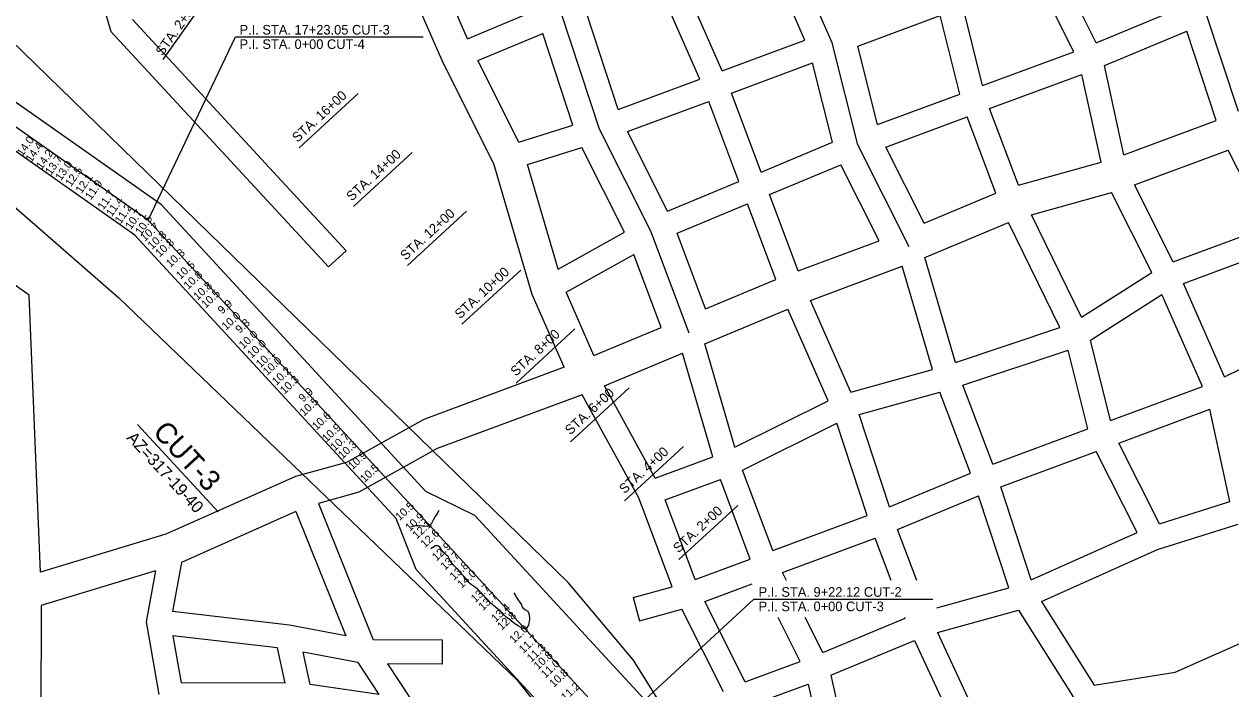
# Model space of a CAD drawing. Extents: x 503330 to 511530, y 1310349 to 1316149.
# Drawn here: x 506410 to 509426, y 1313078 to 1314740 of the extents above; entities that cross this region are included whole.
import ezdxf

# ---------------------------------------------------------------- set-up
doc = ezdxf.new("R2010")
doc.units = 0
for name, color, linetype in [('Level 1', 7, 'Continuous'), ('Level 13', 7, 'Continuous'), ('Level 14', 7, 'Continuous'), ('Level 23', 7, 'Continuous'), ('Level 32', 7, 'Continuous'), ('Level 49', 7, 'Continuous'), ('Level 5', 7, 'Continuous'), ('Level 50', 7, 'Continuous'), ('Level 51', 7, 'Continuous'), ('Level 56', 7, 'Continuous'), ('Level 6', 7, 'Continuous')]:
    doc.layers.add(name, color=color, linetype=linetype)

msp = doc.modelspace()

# ---------------------------------------------------------------- linework, layer by layer
at = {"layer": 'Level 1'}
for points in [[(507377.3, 1313484.3), (507382.6, 1313485.7), (507386.6, 1313486.1), (507392.1, 1313486.3), (507398.9, 1313486.3), (507405.5, 1313486.1), (507411.9, 1313485.7), (507418.2, 1313485.2), (507424, 1313487.5), (507429.2, 1313492.7), (507433.9, 1313500.8), (507438, 1313508), (507441.6, 1313514.3), (507447.6, 1313525.3)], [(507580.8, 1313288.9), (507577.7, 1313291.9), (507574.6, 1313295), (507571.5, 1313298.2), (507567.9, 1313302.1), (507563.8, 1313306.6), (507559.2, 1313311.7), (507554.3, 1313316.9), (507549, 1313322), (507543.5, 1313327.2), (507538.3, 1313331.6), (507533.4, 1313335.3), (507528.7, 1313338.4), (507524.3, 1313342), (507520.1, 1313346.1), (507516.2, 1313350.9), (507512.9, 1313354.9), (507510.2, 1313358.2), (507508.1, 1313360.7), (507505.7, 1313363.6), (507503.1, 1313366.7), (507500.2, 1313370.1), (507496, 1313374.7), (507490.6, 1313380.4), (507483.9, 1313387.3), (507478.7, 1313393.6), (507475, 1313399.3), (507472.8, 1313404.5), (507469.9, 1313409), (507466.4, 1313412.8), (507462.3, 1313415.9), (507458, 1313420.3), (507453.7, 1313425.9), (507449.2, 1313432.8), (507444.3, 1313436.1), (507438.9, 1313435.9), (507427.1, 1313428.4)], [(507634.1, 1313318.6), (507638.1, 1313311.4), (507639.7, 1313308.8), (507640.7, 1313307.2), (507641.2, 1313306.5), (507643, 1313303.9), (507646, 1313299.4), (507650.3, 1313292.9), (507653.2, 1313288.1), (507654.7, 1313284.8), (507654.8, 1313283.1), (507657.2, 1313280.5), (507661.9, 1313277), (507669, 1313272.6), (507672.8, 1313264.5), (507673.4, 1313252.8), (507670.7, 1313237.4), (507665.2, 1313229.5), (507656.7, 1313228.9), (507645.4, 1313235.7), (507637, 1313241), (507631.6, 1313244.8), (507629.2, 1313247.1), (507626.1, 1313249.6), (507622.5, 1313252.2), (507618.4, 1313255), (507614.6, 1313258.1), (507611.3, 1313261.5), (507608.4, 1313265.2), (507604.5, 1313269.3), (507599.4, 1313273.7), (507593.3, 1313278.5), (507588.2, 1313282.6), (507584, 1313286), (507580.8, 1313288.9)]]:
    msp.add_lwpolyline(points, dxfattribs=at)
at = {"layer": 'Level 13'}
for p, q in [((508430.3, 1314693.3), (508302.2, 1314984.7)), ((507848.3, 1314477.4), (507752.6, 1314768.6)), ((508493.9, 1314438.6), (508430.3, 1314693.3)), ((507976.5, 1314222.4), (507848.3, 1314477.4)), ((508622.1, 1314183.7), (508493.9, 1314438.6)), ((508072.4, 1313967.6), (507976.5, 1314222.4))]:
    msp.add_line(p, q, dxfattribs=at)
at = {"layer": 'Level 14'}
for p, q in [((508361.9, 1314699.9), (508258, 1314936.2)), ((507895.3, 1314526.8), (507817.5, 1314763.2)), ((507781.8, 1314487.7), (507706.5, 1314716.8)), ((508543.2, 1314488.9), (508494.2, 1314685.1)), ((508430.6, 1314444.7), (508381, 1314643.1)), ((508018.5, 1314272.5), (507918.5, 1314471.4)), ((507910.6, 1314220), (507804.1, 1314431.9)), ((508659.6, 1314242.7), (508564.1, 1314432.7)), ((508547.4, 1314198.6), (508451.9, 1314388.6)), ((508113.7, 1314028.2), (508042.5, 1314217.5)), ((508002.9, 1313981.9), (507934.2, 1314164.5))]:
    msp.add_line(p, q, dxfattribs=at)
at = {"layer": 'Level 23'}
for p, q in [((507518.7, 1314703.4), (507447.5, 1314865.4)), ((507457.7, 1314643.5), (507369, 1314845.3)), ((507584.7, 1314390.8), (507457.7, 1314643.5)), ((507647, 1314444.9), (507544.4, 1314649.1)), ((509159.1, 1314413.5), (509389.7, 1314499.1)), ((509185.7, 1314338), (509420.1, 1314425)), ((507680, 1314064.3), (507584.7, 1314390.8)), ((507744.9, 1314127.5), (507668.6, 1314388.8)), ((508895.7, 1314337.4), (509101.9, 1314394.6)), ((508928.1, 1314263.4), (509128.2, 1314318.9)), ((508659.6, 1314242.7), (508839, 1314317.6)), ((508661.2, 1314156.7), (508870.7, 1314244.2)), ((508345.2, 1314123.5), (508547.4, 1314198.6)), ((508375.4, 1314049.4), (508605.1, 1314134.7)), ((508113.7, 1314028.2), (508289.3, 1314101.6)), ((507760, 1313882.2), (507680, 1314064.3)), ((507834.5, 1313911.5), (507764.9, 1314070)), ((508111.6, 1313940.6), (508319.5, 1314027.5)), ((507834.5, 1313911.5), (508002.9, 1313981.9)), ((507861, 1313835.9), (508055.9, 1313917.3)), ((507760, 1313882.2), (507409, 1313751.9)), ((507804.8, 1313813.5), (507442.6, 1313679.1)), ((507409, 1313751.9), (507341.6, 1313714.3)), ((507341.6, 1313714.3), (507216.3, 1313644.4)), ((507442.6, 1313679.1), (507380.5, 1313644.5)), ((507216.3, 1313644.4), (507088.8, 1313609.1)), ((507380.5, 1313644.5), (507246.9, 1313569.9)), ((507088.8, 1313609.1), (506764.9, 1313464.7)), ((507246.9, 1313569.9), (507146.4, 1313542)), ((507089.8, 1313521.9), (506803.5, 1313394.2)), ((506764.9, 1313464.7), (506451.4, 1313369.7)), ((506738.6, 1313373.1), (506453.3, 1313286.6))]:
    msp.add_line(p, q, dxfattribs=at)
at = {"layer": 'Level 32'}
for p, q in [((509090.1, 1314693), (508990, 1314892.1)), ((509034, 1314671), (508934.1, 1314869.8)), ((506627.9, 1314721.2), (506592.9, 1314841.3)), ((508099.1, 1314602.4), (507995.7, 1314837.7)), ((508155.4, 1314623.3), (508051.5, 1314859.6)), ((507518.7, 1314703.4), (507683.6, 1314772.3)), ((508805.9, 1314586.4), (508756.3, 1314784.8)), ((509090.1, 1314693), (509299.2, 1314780.4)), ((509445.3, 1314522), (509363.4, 1314771)), ((507215.1, 1314173.7), (506681.6, 1314751.5)), ((508494.2, 1314685.1), (508700.3, 1314761.5)), ((508749.3, 1314565.4), (508700.3, 1314761.5)), ((507171, 1314133), (506627.9, 1314721.2)), ((507544.4, 1314649.1), (507706.5, 1314716.8)), ((509110.5, 1314636.5), (509316.2, 1314722.5)), ((509389.7, 1314499.1), (509316.2, 1314722.5)), ((508155.4, 1314623.3), (508361.9, 1314699.9)), ((508805.9, 1314586.4), (509034, 1314671)), ((508178, 1314567.7), (508381, 1314643.1)), ((509159.1, 1314413.5), (509110.5, 1314636.5)), ((507895.3, 1314526.8), (508099.1, 1314602.4)), ((508823.6, 1314529), (509053.9, 1314614.4)), ((509101.9, 1314394.6), (509053.9, 1314614.4)), ((508252.3, 1314370.2), (508178, 1314567.7)), ((508543.2, 1314488.9), (508749.3, 1314565.4)), ((507918.5, 1314471.4), (508121.8, 1314546.9)), ((508197, 1314347), (508121.8, 1314546.9)), ((508564.1, 1314432.7), (508767.3, 1314508.1)), ((508839, 1314317.6), (508767.3, 1314508.1)), ((508895.7, 1314337.4), (508823.6, 1314529)), ((507647, 1314444.9), (507781.8, 1314487.7)), ((508252.3, 1314370.2), (508430.6, 1314444.7)), ((507668.6, 1314388.8), (507804.1, 1314431.9)), ((509516.7, 1314233), (509420.1, 1314425)), ((508273.5, 1314314), (508451.9, 1314388.6)), ((508018.5, 1314272.5), (508197, 1314347)), ((509228.6, 1314119.3), (509128.2, 1314318.9)), ((509282.3, 1314146), (509185.7, 1314338)), ((508042.5, 1314217.5), (508218.1, 1314290.8)), ((508289.3, 1314101.6), (508218.1, 1314290.8)), ((508345.2, 1314123.5), (508273.5, 1314314)), ((509053.2, 1314007.3), (508928.1, 1314263.4)), ((508999, 1313981.6), (508870.7, 1314244.2)), ((509282.3, 1314146), (509516.7, 1314233)), ((507744.9, 1314127.5), (507910.6, 1314220)), ((507171, 1314133), (507215.1, 1314173.7)), ((509307.8, 1314091.5), (509543.8, 1314179.1)), ((507764.9, 1314070), (507934.2, 1314164.5)), ((508737.8, 1313894.4), (508661.2, 1314156.7)), ((508680.4, 1313876.9), (508605.1, 1314134.7)), ((509053.2, 1314007.3), (509228.6, 1314119.3)), ((509410.4, 1313858.1), (509307.8, 1314091.5)), ((508476.2, 1313820.2), (508375.4, 1314049.4)), ((509075.3, 1313950.3), (509254.2, 1314064.4)), ((509355.3, 1313834.3), (509254.2, 1314064.4)), ((508420.2, 1313798.5), (508319.5, 1314027.5)), ((508737.8, 1313894.4), (508999, 1313981.6)), ((509410.4, 1313858.1), (509646.4, 1313975)), ((508186.8, 1313682.8), (508111.6, 1313940.6)), ((509125.6, 1313749), (509075.3, 1313950.3)), ((508131.4, 1313658.4), (508055.9, 1313917.3)), ((508756.8, 1313837.5), (509019.8, 1313925.2)), ((509069, 1313728), (509019.8, 1313925.2)), ((508476.2, 1313820.2), (508680.4, 1313876.9)), ((507987.9, 1313605.2), (507861, 1313835.9)), ((508831.2, 1313639.8), (508756.8, 1313837.5)), ((507946.8, 1313555.5), (507804.8, 1313813.5)), ((508497.5, 1313763.9), (508699.3, 1313819.9)), ((508775.4, 1313617.8), (508699.3, 1313819.9)), ((509125.6, 1313749), (509355.3, 1313834.3)), ((508186.8, 1313682.8), (508420.2, 1313798.5)), ((509146.5, 1313692.8), (509373.7, 1313777.1)), ((509424, 1313546.5), (509373.7, 1313777.1)), ((508573.3, 1313533.3), (508497.5, 1313763.9)), ((508205.7, 1313625.2), (508441.5, 1313742.1)), ((508517.4, 1313511.2), (508441.5, 1313742.1)), ((508831.2, 1313639.8), (509069, 1313728)), ((509248.1, 1313490.6), (509146.5, 1313692.8)), ((507987.9, 1313605.2), (508131.4, 1313658.4)), ((508851.2, 1313583.2), (509089.9, 1313671.8)), ((509191.9, 1313468.9), (509089.9, 1313671.8)), ((508281.5, 1313423.7), (508205.7, 1313625.2)), ((508012.8, 1313550.4), (508150.5, 1313601.5)), ((508225.3, 1313402.8), (508150.5, 1313601.5)), ((508573.3, 1313533.3), (508775.4, 1313617.8)), ((508927.5, 1313351), (508851.2, 1313583.2)), ((507146.4, 1313542), (507282.6, 1313200.7)), ((508030.3, 1313333.3), (507946.8, 1313555.5)), ((508087.5, 1313351.7), (508012.8, 1313550.4)), ((508593.2, 1313476.6), (508795.3, 1313561.1)), ((508871.1, 1313330.6), (508795.3, 1313561.1)), ((509248.1, 1313490.6), (509424, 1313546.5)), ((507089.8, 1313521.9), (507214.1, 1313210.6)), ((508281.5, 1313423.7), (508517.4, 1313511.2)), ((508641.2, 1313349.2), (508593.2, 1313476.6)), ((509243.5, 1313426.2), (509444.7, 1313490.1)), ((508305.8, 1313368.7), (508537.4, 1313454.6)), ((508577.1, 1313349.2), (508537.4, 1313454.6)), ((508927.5, 1313351), (509191.9, 1313468.9)), ((508953.2, 1313296.7), (509243.5, 1313426.2)), ((506803.5, 1313394.2), (506781.2, 1313271.6)), ((508087.5, 1313351.7), (508225.3, 1313402.8)), ((506738.6, 1313373.1), (506715.5, 1313245.6)), ((508315.6, 1313349.2), (508305.8, 1313368.7)), ((507932.7, 1313306.2), (508030.3, 1313333.3)), ((508111.8, 1313296.7), (508230.4, 1313340.7)), ((508691.9, 1313280.8), (508871.1, 1313330.6)), ((507932.7, 1313306.2), (507948.7, 1313248.4)), ((508212.9, 1313095.7), (508111.8, 1313296.7)), ((508953.2, 1313296.7), (509084.8, 1313087.7)), ((506453.3, 1313286.6), (506452.1, 1312982.5)), ((507073.3, 1313237.5), (506781.2, 1313271.6)), ((507948.7, 1313248.4), (508054.2, 1313277.7)), ((508158.5, 1313070.4), (508054.2, 1313277.7)), ((508693, 1313218.9), (508895.9, 1313275.2)), ((508895.9, 1313275.2), (509042.6, 1313042.1)), ((506715.5, 1313245.6), (506747, 1313064.3)), ((507214.1, 1313210.6), (507073.3, 1313237.5)), ((508350.3, 1313146.7), (508295.2, 1313256.3)), ((508406.4, 1313168.7), (508362.3, 1313256.3)), ((508406.4, 1313168.7), (508612.6, 1313254.8)), ((508612.6, 1313254.8), (508612, 1313256.3)), ((509287.5, 1313119.5), (509577.4, 1313248.8)), ((506782.4, 1313211), (506802.8, 1313093.5)), ((507043.9, 1313180.6), (506782.4, 1313211)), ((508693, 1313218.9), (508951.9, 1312662.9)), ((507063.1, 1313092.5), (507043.9, 1313180.6)), ((507456.1, 1313200.1), (507282.6, 1313200.7)), ((507455.9, 1313140.1), (507456.1, 1313200.1)), ((508426.8, 1313112.2), (508635.8, 1313199.5)), ((508635.8, 1313199.5), (508896.2, 1312640.4)), ((507125.3, 1313089.1), (507107.7, 1313169.9)), ((507244.2, 1313143.7), (507107.7, 1313169.9)), ((507244.2, 1313143.7), (507296.7, 1313064.3)), ((508212.9, 1313095.7), (508350.3, 1313146.7)), ((507455.9, 1313140.1), (507318.2, 1313140.6)), ((507318.2, 1313140.6), (507374.8, 1313054.9)), ((508426.8, 1313112.2), (508451.6, 1312998.7)), ((509084.8, 1313087.7), (509287.5, 1313119.5)), ((507063.1, 1313092.5), (506802.8, 1313093.5)), ((507296.7, 1313064.3), (507125.3, 1313089.1)), ((508238.4, 1313041.2), (508370.2, 1313090.1)), ((508370.2, 1313090.1), (508395.4, 1312974.4))]:
    msp.add_line(p, q, dxfattribs=at)
msp.add_lwpolyline([(506451.4, 1313369.7), (506423.2, 1314062.5), (506145.9, 1314259.3), (505991.1, 1314259.9)], dxfattribs=at)
at = {"layer": 'Level 5'}
for points in [[(505794, 1315948.5), (505744.2, 1315800.6), (505760.3, 1315617.2), (505843.1, 1315416.9), (505891.3, 1314808.3), (506024, 1314599.6), (506647.4, 1314056), (507642.5, 1313099.9), (507702.7, 1313024.1), (507718.9, 1312844.3), (507743.6, 1312727.6), (507768.6, 1312719.2), (507933.4, 1312101.9), (507890.2, 1311593.7)], [(508324.1, 1311750.7), (508174.9, 1312042.9), (508101.5, 1312576.5), (508071.4, 1312743.4), (508047.3, 1312868.5), (508036.4, 1312983.7), (507933.5, 1313150.3), (507770.5, 1313344.2), (506282.9, 1314790.5), (506133.6, 1315024.3), (506134.1, 1315191), (506100.8, 1315216.1), (506088.6, 1315786), (506110.2, 1315948.5)]]:
    msp.add_lwpolyline(points, dxfattribs=at)
at = {"layer": 'Level 50'}
for p, q in [((506753.5, 1314288), (506162.3, 1314703.9)), ((506687.2, 1314212.4), (506072.1, 1314645.1)), ((507414, 1313571.4), (506753.5, 1314288)), ((507340.5, 1313503.7), (506687.2, 1314212.4)), ((507536.9, 1313512), (507414, 1313571.4)), ((507389.8, 1313376.4), (507340.5, 1313503.7)), ((507981.8, 1313029.4), (507536.9, 1313512)), ((507794.7, 1312937.3), (507389.8, 1313376.4))]:
    msp.add_line(p, q, dxfattribs=at)
at = {"layer": 'Level 51'}
msp.add_line((506895.6, 1313520.7), (506693.8, 1313739.5), dxfattribs=at)
at = {"layer": 'Level 56'}
for p, q in [((506758.1, 1314651.5), (506873.2, 1314815.1)), ((506720.3, 1314250.2), (506938.8, 1314708.1)), ((506938.8, 1314708.1), (507407.7, 1314708.1)), ((507097.8, 1314430.8), (507244.9, 1314566.4)), ((507233.4, 1314283.8), (507380.4, 1314419.3)), ((507368.9, 1314136.7), (507516, 1314272.3)), ((507504.5, 1313989.7), (507651.6, 1314125.2)), ((507640.1, 1313842.6), (507787.1, 1313978.2)), ((507775.6, 1313695.6), (507922.7, 1313831.1)), ((507911.2, 1313548.5), (508058.2, 1313684.1)), ((508046.7, 1313401.5), (508193.8, 1313537)), ((507888.2, 1312983.3), (508234.3, 1313302.4)), ((508234.3, 1313302.4), (508681.5, 1313302.4))]:
    msp.add_line(p, q, dxfattribs=at)
at = {"layer": 'Level 6'}
for p, q in [((506720.3, 1314250.2), (506117.2, 1314674.5)), ((507888.2, 1312983.3), (506720.3, 1314250.2))]:
    msp.add_line(p, q, dxfattribs=at)

# ---------------------------------------------------------------- texts
at = {"layer": 'Level 49'}
for s, rotation, p in [('14.0 ', 54.8711, (506406.4, 1314408.2)), ('14.4 ', 54.8711, (506428.4, 1314393.2)), ('14.2 ', 54.8711, (506454.4, 1314375.2)), ('13.7 ', 54.8711, (506477.4, 1314361.2)), ('13.0 ', 54.8711, (506502.4, 1314347.2)), ('12.5 ', 54.8711, (506527.4, 1314332.2)), ('12.1 ', 54.8711, (506553.4, 1314315.2)), ('11.9 ', 54.8711, (506577.4, 1314299.2)), ('11.7 ', 54.8711, (506608.4, 1314274.2)), ('11.4 ', 54.8711, (506629.4, 1314257.2)), ('11.2 ', 54.8711, (506651.4, 1314239.2)), ('10.7 ', 54.8711, (506677.4, 1314225.2)), ('10.5 ', 54.8711, (506702.4, 1314211.2)), ('10.7 ', 42.6723, (506712, 1314195.7)), ('10.8 ', 42.6723, (506730, 1314175.7)), ('10.8 ', 42.6723, (506749, 1314156.7)), ('10.8 ', 42.6723, (506776, 1314130.7)), ('10.5 ', 42.6723, (506801, 1314100.7)), ('10.8 ', 42.6723, (506820, 1314075.7)), ('10.8 ', 42.6723, (506844, 1314048.7)), ('10.5 ', 42.6723, (506864, 1314028.7)), ('9.9', 42.6723, (506905.3, 1314013.8)), ('10.0 ', 42.6723, (506915, 1313973.7)), ('9.8', 42.6723, (506949.4, 1313965.8)), ('10.0 ', 42.6723, (506958, 1313926.7)), ('10.0 ', 42.6723, (506979, 1313903.7)), ('10.1 ', 42.6723, (507001, 1313879.7)), ('10.0 ', 42.6723, (507018, 1313860.7)), ('10.2 ', 42.6723, (507041, 1313835.7)), ('10.3 ', 42.6723, (507061, 1313813.7)), ('9.9', 42.6723, (507107.3, 1313793.8)), ('10.5 ', 42.6723, (507110, 1313758.7)), ('10.6 ', 42.6723, (507141, 1313723.7)), ('10.9 ', 42.6723, (507166, 1313693.7)), ('10.7 ', 42.6723, (507187, 1313671.7)), ('10.3 ', 42.6723, (507206, 1313651.7)), ('10.9 ', 42.6723, (507231, 1313624.7)), ('10.5 ', 42.6723, (507261, 1313592.7)), ('10.5 ', 42.6723, (507349, 1313497.7)), ('10.9 ', 42.6723, (507374, 1313470.7)), ('12.1 ', 42.6723, (507392, 1313451.7)), ('12.6 ', 42.6723, (507412, 1313429.7)), ('12.9 ', 42.6723, (507441, 1313396.7)), ('13.7 ', 42.6723, (507462, 1313373.7)), ('13.8 ', 42.6723, (507485, 1313348.7)), ('14.0 ', 42.6723, (507504, 1313328.7)), ('13.7 ', 42.6723, (507538, 1313292.7)), ('13.7 ', 42.6723, (507557, 1313272.7)), ('13.4 ', 42.6723, (507589, 1313243.7)), ('12.8 ', 42.6723, (507604, 1313223.7)), ('12.0 ', 42.6723, (507634, 1313190.7)), ('11.7 ', 42.6723, (507658, 1313165.7)), ('11.3 ', 42.6723, (507678, 1313143.7)), ('10.8 ', 42.6723, (507695, 1313124.7)), ('11.0 ', 42.6723, (507713, 1313103.7)), ('10.8 ', 42.6723, (507734, 1313080.7)), ('11.2 ', 42.6723, (507763, 1313046.7))]:
    msp.add_text(s, height=20, rotation=rotation, dxfattribs=at).set_placement(p)
at = {"layer": 'Level 51'}
for s, height, p in [('AZ=317-19-40', 30, (506664.9, 1313704.5)), ('CUT-3', 52, (506729.5, 1313718.5))]:
    msp.add_text(s, height=height, rotation=312.6723, dxfattribs=at).set_placement(p)
at = {"layer": 'Level 56'}
for s, rotation, p in [('STA. 2+00', 54.7657, (506756.6, 1314659.4)), ('STA. 16+00', 42.6723, (507093.5, 1314443.2)), ('STA. 14+00', 42.6723, (507229.1, 1314296.1)), ('STA. 12+00', 42.6723, (507363.8, 1314148.3)), ('STA. 10+00', 42.6723, (507499.9, 1314001.8)), ('STA. 8+00', 42.6723, (507639.5, 1313858.5)), ('STA. 6+00', 42.6723, (507775.4, 1313711.7)), ('STA. 4+00', 42.6723, (507910.9, 1313564.6)), ('STA. 2+00', 42.6723, (508045.7, 1313416.8))]:
    msp.add_text(s, height=24, rotation=rotation, dxfattribs=at).set_placement(p)
for s, p in [('P.I. STA. 17+23.05 CUT-3', (506948.8, 1314714.1)), ('P.I. STA. 0+00 CUT-4', (506948.8, 1314678.1)), ('P.I. STA. 9+22.12 CUT-2', (508246, 1313308.4)), ('P.I. STA. 0+00 CUT-3', (508246, 1313272.4))]:
    msp.add_text(s, height=24, dxfattribs=at).set_placement(p)

doc.saveas('drawing.dxf')
